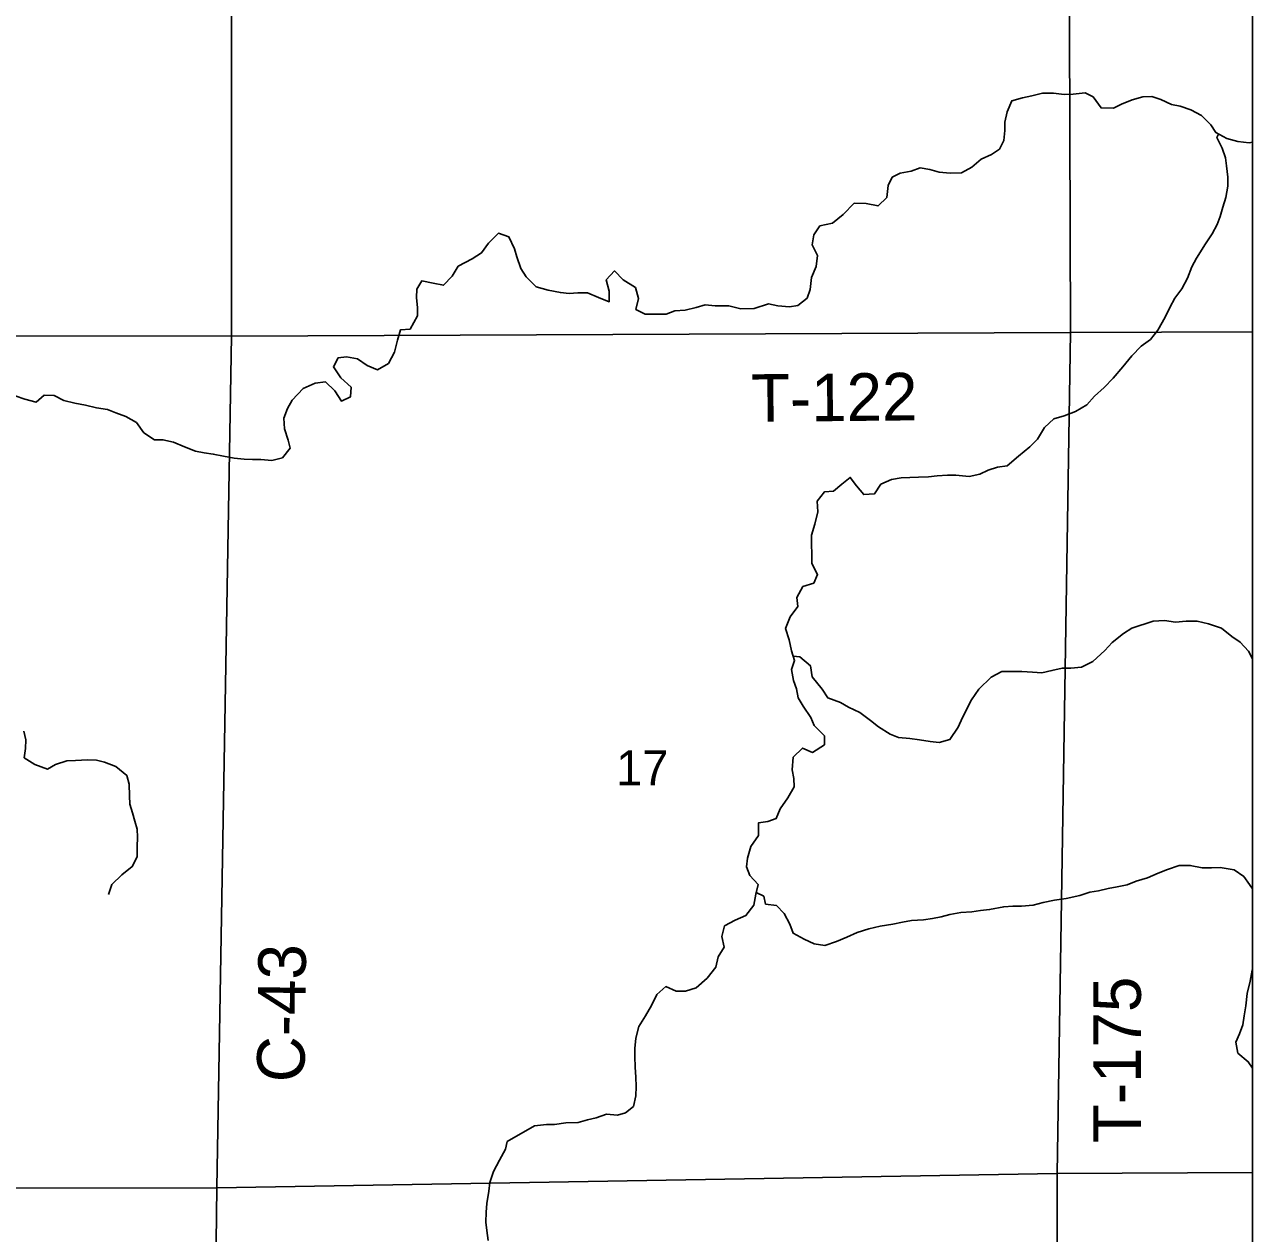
# Model space of a CAD drawing. Extents: x 1772825 to 1773716, y 1138558 to 1139032.
# Drawn here: x 1772831.426 to 1772832.158, y 1138562.599 to 1138563.32 of the extents above; entities that cross this region are included whole.
import ezdxf

# ---------------------------------------------------------------- set-up
doc = ezdxf.new("R2010")
doc.units = 0
for name, color, linetype in [('GM_X_County_Road_Text', 7, 'Continuous'), ('GM_X_Minor_River', 7, 'Continuous'), ('GM_X_Section', 7, 'Continuous'), ('GM_X_Section_Text', 7, 'Continuous'), ('GM_X_Township', 7, 'Continuous'), ('GM_X_Township_Road_Text', 7, 'Continuous')]:
    doc.layers.add(name, color=color, linetype=linetype)

msp = doc.modelspace()

# ---------------------------------------------------------------- linework, layer by layer
at = {"layer": 'GM_X_Minor_River'}
for points in [[(1772831.78277, 1138563.16788), (1772831.79012, 1138563.16328), (1772831.79179, 1138563.15683), (1772831.79023, 1138563.1502), (1772831.79589, 1138563.14732), (1772831.80232, 1138563.14748), (1772831.80838, 1138563.14744), (1772831.8135, 1138563.14931), (1772831.81974, 1138563.14984), (1772831.82618, 1138563.15133), (1772831.83168, 1138563.153), (1772831.83754, 1138563.1524), (1772831.84567, 1138563.15235), (1772831.85285, 1138563.15061), (1772831.86079, 1138563.15075), (1772831.86932, 1138563.15355), (1772831.87499, 1138563.15238), (1772831.8818, 1138563.15177), (1772831.88691, 1138563.1525), (1772831.89242, 1138563.15702), (1772831.89415, 1138563.16213), (1772831.89495, 1138563.16933), (1772831.89783, 1138563.17577), (1772831.89862, 1138563.1824), (1772831.89544, 1138563.18867), (1772831.89642, 1138563.19474), (1772831.90005, 1138563.20003), (1772831.90744, 1138563.20169), (1772831.9139, 1138563.20677), (1772831.92037, 1138563.21356), (1772831.92756, 1138563.21333), (1772831.93473, 1138563.21197), (1772831.93987, 1138563.21687), (1772831.94067, 1138563.22407), (1772831.94316, 1138563.22899), (1772831.9479, 1138563.23142), (1772831.95434, 1138563.23272), (1772831.95984, 1138563.23458), (1772831.96551, 1138563.2336), (1772831.97117, 1138563.23205), (1772831.9776, 1138563.23145), (1772831.98441, 1138563.2316), (1772831.99067, 1138563.23498), (1772831.99619, 1138563.23988), (1772832.00226, 1138563.2425), (1772832.007, 1138563.24569), (1772832.00968, 1138563.25099), (1772832.01028, 1138563.25686), (1772832.01031, 1138563.26179), (1772832.01167, 1138563.26804), (1772832.01436, 1138563.27447), (1772832.0208, 1138563.27634), (1772832.02629, 1138563.27744), (1772832.03273, 1138563.27911), (1772832.03936, 1138563.27908), (1772832.04559, 1138563.27828), (1772832.05108, 1138563.27863), (1772832.05808, 1138563.27935), (1772832.06299, 1138563.27686), (1772832.06768, 1138563.27038), (1772832.07506, 1138563.27015), (1772832.0798, 1138563.27259), (1772832.08625, 1138563.27521), (1772832.0925, 1138563.27688), (1772832.09798, 1138563.27723), (1772832.10327, 1138563.2753), (1772832.10969, 1138563.27242), (1772832.11479, 1138563.27145), (1772832.1212, 1138563.26913), (1772832.12762, 1138563.26588), (1772832.13307, 1138563.26035), (1772832.13607, 1138563.25559), (1772832.14267, 1138563.25214), (1772832.14928, 1138563.25039), (1772832.1559, 1138563.2496), (1772832.15791, 1138563.25001)], [(1772832.13767, 1138563.25475), (1772832.13662, 1138563.25274), (1772832.1398, 1138563.24628), (1772832.14185, 1138563.24058), (1772832.14239, 1138563.23583), (1772832.14329, 1138563.229), (1772832.14326, 1138563.22369), (1772832.14209, 1138563.21687), (1772832.14035, 1138563.21119), (1772832.13862, 1138563.2057), (1772832.13689, 1138563.20078), (1772832.13383, 1138563.1953), (1772832.13001, 1138563.18925), (1772832.12447, 1138563.18075), (1772832.1218, 1138563.17565), (1772832.11911, 1138563.16883), (1772832.11586, 1138563.16241), (1772832.11166, 1138563.15693), (1772832.1086, 1138563.15145), (1772832.10592, 1138563.14559), (1772832.10152, 1138563.13783), (1772832.09714, 1138563.13236), (1772832.09163, 1138563.12841), (1772832.08592, 1138563.12256), (1772832.08059, 1138563.11596), (1772832.07488, 1138563.10916), (1772832.06955, 1138563.10369), (1772832.06365, 1138563.09861), (1772832.05908, 1138563.09332), (1772832.05244, 1138563.08938), (1772832.04561, 1138563.08676), (1772832.03955, 1138563.08509), (1772832.03384, 1138563.07981), (1772832.02983, 1138563.07282), (1772832.02508, 1138563.06829), (1772832.01842, 1138563.06283), (1772832.01158, 1138563.05699), (1772832.0059, 1138563.05626), (1772832.0004, 1138563.0544), (1772831.99528, 1138563.05196), (1772831.98903, 1138563.05067), (1772831.98109, 1138563.05147), (1772831.97617, 1138563.0515), (1772831.96993, 1138563.05097), (1772831.96482, 1138563.05043), (1772831.95876, 1138563.05027), (1772831.95366, 1138563.05011), (1772831.94855, 1138563.04976), (1772831.94268, 1138563.04884), (1772831.93642, 1138563.04603), (1772831.9326, 1138563.04037), (1772831.92617, 1138563.03983), (1772831.92185, 1138563.04517), (1772831.91809, 1138563.05012), (1772831.91315, 1138563.04616), (1772831.90821, 1138563.04183), (1772831.90272, 1138563.04148), (1772831.89834, 1138563.03601), (1772831.89868, 1138563.02956), (1772831.89693, 1138563.02217), (1772831.895, 1138563.01574), (1772831.89497, 1138563.00967), (1772831.89513, 1138563.00493), (1772831.89529, 1138562.99886), (1772831.89865, 1138562.9922), (1772831.89635, 1138562.9871), (1772831.88991, 1138562.98505), (1772831.88627, 1138562.97843), (1772831.88681, 1138562.97312), (1772831.88224, 1138562.96707), (1772831.87955, 1138562.96007), (1772831.88159, 1138562.95324), (1772831.88306, 1138562.94678), (1772831.88492, 1138562.94089), (1772831.883, 1138562.93559), (1772831.88429, 1138562.92914), (1772831.88615, 1138562.92401), (1772831.88706, 1138562.91869), (1772831.89006, 1138562.91375), (1772831.89456, 1138562.90708), (1772831.89661, 1138562.90214), (1772831.90282, 1138562.89604), (1772831.90279, 1138562.89073), (1772831.89557, 1138562.88622), (1772831.88954, 1138562.88872), (1772831.88402, 1138562.88325), (1772831.88341, 1138562.87586), (1772831.88451, 1138562.87073), (1772831.88467, 1138562.86561), (1772831.88085, 1138562.85919), (1772831.87627, 1138562.85257), (1772831.87397, 1138562.84671), (1772831.86904, 1138562.84503), (1772831.86336, 1138562.84411), (1772831.86332, 1138562.83672), (1772831.85874, 1138562.83011), (1772831.85681, 1138562.8231), (1772831.85621, 1138562.81799), (1772831.85826, 1138562.81285), (1772831.86315, 1138562.80752), (1772831.86179, 1138562.80165)], [(1772831.42012, 1138563.09879), (1772831.42597, 1138563.09667), (1772831.43277, 1138563.09493), (1772831.43752, 1138563.09908), (1772831.44338, 1138563.09885), (1772831.44923, 1138563.09597), (1772831.45584, 1138563.09442), (1772831.46208, 1138563.09325), (1772831.46869, 1138563.09151), (1772831.47531, 1138563.09052), (1772831.48021, 1138563.0886), (1772831.48625, 1138563.08648), (1772831.49248, 1138563.08284), (1772831.49698, 1138563.07675), (1772831.5032, 1138563.07254), (1772831.50831, 1138563.07251), (1772831.51454, 1138563.07115), (1772831.52114, 1138563.06827), (1772831.52775, 1138563.06577), (1772831.53285, 1138563.06479), (1772831.53833, 1138563.064), (1772831.54438, 1138563.06283), (1772831.5508, 1138563.06166), (1772831.55666, 1138563.06105), (1772831.56177, 1138563.06084), (1772831.56669, 1138563.06081), (1772831.57331, 1138563.0602), (1772831.57956, 1138563.06169), (1772831.58413, 1138563.06754), (1772831.58302, 1138563.07228), (1772831.58079, 1138563.07912), (1772831.58045, 1138563.08538), (1772831.58257, 1138563.09125), (1772831.58543, 1138563.09616), (1772831.59191, 1138563.10314), (1772831.59911, 1138563.10633), (1772831.60517, 1138563.10705), (1772831.61081, 1138563.10171), (1772831.61475, 1138563.09562), (1772831.62006, 1138563.09806), (1772831.62047, 1138563.10393), (1772831.61445, 1138563.10946), (1772831.60995, 1138563.11594), (1772831.61282, 1138563.12142), (1772831.61774, 1138563.12196), (1772831.62436, 1138563.12079), (1772831.63001, 1138563.11677), (1772831.63623, 1138563.11427), (1772831.64288, 1138563.11803), (1772831.64632, 1138563.12484), (1772831.64806, 1138563.13184), (1772831.64999, 1138563.13809), (1772831.65567, 1138563.13844), (1772831.66007, 1138563.14638), (1772831.66009, 1138563.15112), (1772831.65956, 1138563.15738), (1772831.65959, 1138563.16231), (1772831.66265, 1138563.16722), (1772831.66945, 1138563.16586), (1772831.67568, 1138563.16468), (1772831.68082, 1138563.16996), (1772831.68426, 1138563.17601), (1772831.69261, 1138563.18033), (1772831.69831, 1138563.1839), (1772831.7025, 1138563.18975), (1772831.7084, 1138563.1956), (1772831.71463, 1138563.19348), (1772831.71799, 1138563.18625), (1772831.71929, 1138563.18151), (1772831.72171, 1138563.17467), (1772831.7249, 1138563.16972), (1772831.73091, 1138563.16362), (1772831.73809, 1138563.16168), (1772831.74527, 1138563.16031), (1772831.75056, 1138563.15971), (1772831.75567, 1138563.16006), (1772831.76135, 1138563.16003), (1772831.76795, 1138563.15734), (1772831.77437, 1138563.15484), (1772831.77441, 1138563.1611), (1772831.77256, 1138563.16793), (1772831.7775, 1138563.17321), (1772831.78277, 1138563.16788)], [(1772831.88407, 1138562.9436), (1772831.88796, 1138562.94315), (1772831.89436, 1138562.93781), (1772831.89546, 1138562.93116), (1772831.90128, 1138562.92392), (1772831.90466, 1138562.91878), (1772831.91221, 1138562.9159), (1772831.91711, 1138562.91321), (1772831.9239, 1138562.90995), (1772831.93011, 1138562.90518), (1772831.93501, 1138562.90136), (1772831.94198, 1138562.89696), (1772831.94689, 1138562.89503), (1772831.9537, 1138562.89443), (1772831.95937, 1138562.89364), (1772831.96579, 1138562.89265), (1772831.97108, 1138562.89205), (1772831.97753, 1138562.89391), (1772831.98249, 1138562.90128), (1772831.98498, 1138562.90696), (1772831.99034, 1138562.91754), (1772831.99473, 1138562.92397), (1772832.00214, 1138562.93094), (1772832.00841, 1138562.93451), (1772832.02032, 1138562.93444), (1772832.02675, 1138562.93403), (1772832.03224, 1138562.93362), (1772832.0383, 1138562.93491), (1772832.04436, 1138562.93639), (1772832.04966, 1138562.93637), (1772832.0559, 1138562.9369), (1772832.06273, 1138562.94046), (1772832.06996, 1138562.94687), (1772832.07434, 1138562.95178), (1772832.08099, 1138562.95705), (1772832.08592, 1138562.96024), (1772832.09881, 1138562.96434), (1772832.10544, 1138562.96487), (1772832.11205, 1138562.96389), (1772832.11848, 1138562.96442), (1772832.12492, 1138562.96439), (1772832.13172, 1138562.96283), (1772832.13946, 1138562.96032), (1772832.14567, 1138562.95536), (1772832.15057, 1138562.95192), (1772832.15546, 1138562.94658), (1772832.15791, 1138562.94199)], [(1772831.42539, 1138562.8989), (1772831.42649, 1138562.89377), (1772831.42627, 1138562.88846), (1772831.42548, 1138562.88297), (1772831.43189, 1138562.87895), (1772831.43944, 1138562.87626), (1772831.44419, 1138562.87888), (1772831.45101, 1138562.88112), (1772831.45612, 1138562.88128), (1772831.46331, 1138562.88181), (1772831.46861, 1138562.88159), (1772831.47352, 1138562.88043), (1772831.48031, 1138562.87773), (1772831.48671, 1138562.87239), (1772831.48819, 1138562.86726), (1772831.48834, 1138562.86024), (1772831.4885, 1138562.85531), (1772831.49018, 1138562.85018), (1772831.49147, 1138562.84525), (1772831.49296, 1138562.8405), (1772831.49312, 1138562.83576), (1772831.4929, 1138562.82988), (1772831.49286, 1138562.824), (1772831.48999, 1138562.81814), (1772831.48372, 1138562.81324), (1772831.47782, 1138562.8074), (1772831.47589, 1138562.80153)], [(1772831.86204, 1138562.80271), (1772831.86651, 1138562.80048), (1772831.86762, 1138562.79574), (1772831.87405, 1138562.79494), (1772831.87875, 1138562.79017), (1772831.88212, 1138562.78371), (1772831.88398, 1138562.77839), (1772831.89058, 1138562.77494), (1772831.89661, 1138562.77206), (1772831.90304, 1138562.77108), (1772831.90986, 1138562.7735), (1772831.91612, 1138562.77612), (1772831.92219, 1138562.77893), (1772831.9292, 1138562.78098), (1772831.93602, 1138562.78265), (1772831.94341, 1138562.78374), (1772831.94928, 1138562.78504), (1772831.95458, 1138562.78596), (1772831.96177, 1138562.78648), (1772831.96707, 1138562.78721), (1772831.97237, 1138562.78813), (1772831.97749, 1138562.78962), (1772831.98411, 1138562.79072), (1772831.99055, 1138562.79125), (1772831.99585, 1138562.79198), (1772832.00115, 1138562.79252), (1772832.00967, 1138562.79418), (1772832.01497, 1138562.79453), (1772832.02027, 1138562.7945), (1772832.02708, 1138562.79522), (1772832.03314, 1138562.7967), (1772832.03996, 1138562.79818), (1772832.04678, 1138562.79909), (1772832.05492, 1138562.80094), (1772832.06098, 1138562.8028), (1772832.0661, 1138562.80372), (1772832.07197, 1138562.80502), (1772832.07727, 1138562.80613), (1772832.08314, 1138562.80723), (1772832.08864, 1138562.80948), (1772832.09527, 1138562.81133), (1772832.10172, 1138562.81414), (1772832.10722, 1138562.81639), (1772832.11423, 1138562.81881), (1772832.12085, 1138562.81878), (1772832.12784, 1138562.81741), (1772832.13352, 1138562.81738), (1772832.13863, 1138562.81754), (1772832.14694, 1138562.81616), (1772832.15278, 1138562.81215), (1772832.15616, 1138562.80739), (1772832.15791, 1138562.80483)], [(1772831.86179, 1138562.80165), (1772831.86062, 1138562.79521), (1772831.85585, 1138562.78898), (1772831.84941, 1138562.78617), (1772831.84314, 1138562.78279), (1772831.84159, 1138562.77654), (1772831.84288, 1138562.77009), (1772831.83944, 1138562.76442), (1772831.83789, 1138562.75817), (1772831.83275, 1138562.75156), (1772831.82628, 1138562.74591), (1772831.81984, 1138562.74386), (1772831.81435, 1138562.74389), (1772831.80813, 1138562.74658), (1772831.8028, 1138562.74187), (1772831.79955, 1138562.73525), (1772831.79611, 1138562.7292), (1772831.7921, 1138562.72277), (1772831.79017, 1138562.71577), (1772831.78975, 1138562.7097), (1772831.78973, 1138562.70496), (1772831.78988, 1138562.69851), (1772831.79022, 1138562.69263), (1772831.79038, 1138562.68713), (1772831.79034, 1138562.68145), (1772831.78879, 1138562.6752), (1772831.78404, 1138562.67143), (1772831.77931, 1138562.66994), (1772831.77269, 1138562.67055), (1772831.76662, 1138562.66831), (1772831.76151, 1138562.6672), (1772831.75582, 1138562.66552), (1772831.74845, 1138562.66537), (1772831.74182, 1138562.66446), (1772831.7369, 1138562.6643), (1772831.7299, 1138562.66358), (1772831.71364, 1138562.65427)], [(1772832.15791, 1138562.75677), (1772832.15775, 1138562.75637), (1772832.15658, 1138562.74974), (1772832.15484, 1138562.74254), (1772832.15404, 1138562.73515), (1772832.15306, 1138562.72909), (1772832.15208, 1138562.72379), (1772832.15016, 1138562.71849), (1772832.14805, 1138562.71357), (1772832.14914, 1138562.70693), (1772832.15536, 1138562.70177), (1772832.15791, 1138562.69802)], [(1772831.71364, 1138562.65427), (1772831.71248, 1138562.64975), (1772831.70903, 1138562.64313), (1772831.7054, 1138562.63631), (1772831.70328, 1138562.62987), (1772831.70269, 1138562.62474), (1772831.70152, 1138562.61735), (1772831.70112, 1138562.61222), (1772831.70091, 1138562.60615), (1772831.70145, 1138562.60122), (1772831.70219, 1138562.59533)]]:
    msp.add_lwpolyline(points, dxfattribs=at)
at = {"layer": 'GM_X_Section'}
for p, q in [((1772832.15791, 1138563.1369), (1772832.15791, 1138563.6228)), ((1772832.15791, 1138562.63579), (1772832.15791, 1138563.1369)), ((1772832.15791, 1138562.13272), (1772832.15791, 1138562.63579))]:
    msp.add_line(p, q, dxfattribs=at)
for points in [[(1772831.00639, 1138563.63704), (1772831.5492, 1138563.62856), (1772831.54916, 1138563.13419), (1772831.01426, 1138563.13506), (1772831.01485, 1138563.13809)], [(1772831.5492, 1138563.62856), (1772832.04788, 1138563.62167), (1772832.04941, 1138563.13639), (1772831.54916, 1138563.13419)], [(1772831.01426, 1138563.13506), (1772831.54916, 1138563.13419), (1772831.54038, 1138562.62671), (1772831.01723, 1138562.62641), (1772831.0168, 1138562.63735)], [(1772831.54916, 1138563.13419), (1772832.04941, 1138563.13639), (1772832.04141, 1138562.6351), (1772831.54038, 1138562.62671)], [(1772832.04141, 1138562.6351), (1772832.04134, 1138562.13141), (1772831.53426, 1138562.12489), (1772831.54038, 1138562.62671)], [(1772831.01723, 1138562.62641), (1772831.54038, 1138562.62671), (1772831.53426, 1138562.12489), (1772831.0185, 1138562.12561), (1772831.01894, 1138562.13564)]]:
    msp.add_lwpolyline(points, close=True, dxfattribs=at)
for points in [[(1772832.15791, 1138563.6228), (1772832.04788, 1138563.62167), (1772832.04941, 1138563.13639), (1772832.15791, 1138563.1369)], [(1772832.15791, 1138563.1369), (1772832.04941, 1138563.13639), (1772832.04141, 1138562.6351), (1772832.15791, 1138562.63579)], [(1772832.15791, 1138562.63579), (1772832.04141, 1138562.6351), (1772832.04134, 1138562.13141), (1772832.15791, 1138562.13272)]]:
    msp.add_lwpolyline(points, dxfattribs=at)
at = {"layer": 'GM_X_Township'}
msp.add_line((1772832.15791, 1138561.13315), (1772832.15791, 1138564.17965), dxfattribs=at)

# ---------------------------------------------------------------- texts
at = {"layer": 'GM_X_County_Road_Text'}
msp.add_text('C-43', height=0.028409, rotation=89.31207, dxfattribs=at).set_placement((1772831.59269, 1138562.68945))
at = {"layer": 'GM_X_Section_Text'}
msp.add_text('17', height=0.020928, rotation=0.00001, dxfattribs=at).set_placement((1772831.77853, 1138562.86649))
at = {"layer": 'GM_X_Township_Road_Text'}
for s, rotation, p in [('T-122', 0.56053, (1772831.85908, 1138563.08315)), ('T-175', 90, (1772832.09138, 1138562.65329))]:
    msp.add_text(s, height=0.028409, rotation=rotation, dxfattribs=at).set_placement(p)

doc.saveas('drawing.dxf')
